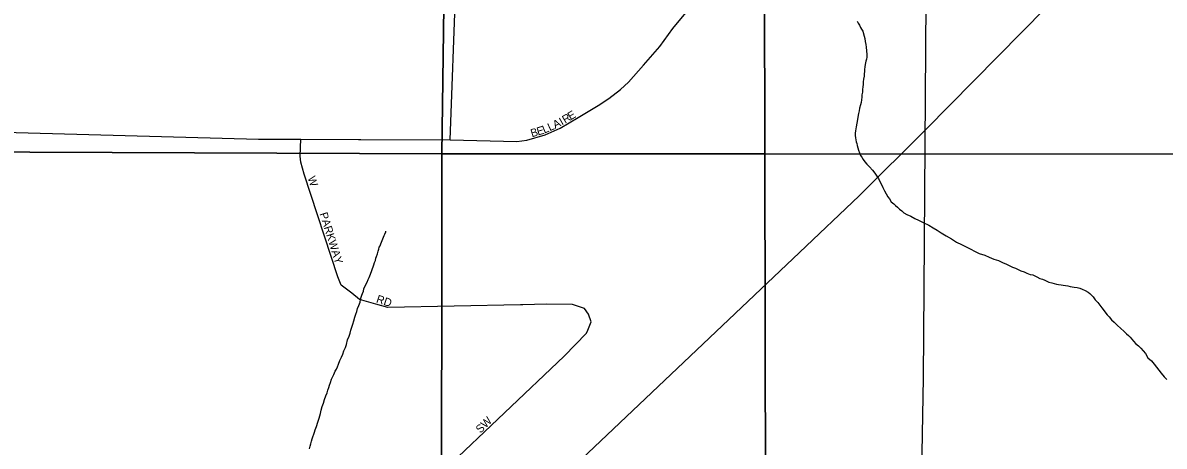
# Model space of a CAD drawing. Extents: x 2010165 to 2382125, y 1060529 to 1407316.
# Drawn here: x 2160411 to 2167540, y 1249702 to 1252344 of the extents above; entities that cross this region are included whole.
import ezdxf

# ---------------------------------------------------------------- set-up
doc = ezdxf.new("R2010")
doc.units = 0
for name, color, linetype in [('GM_X_City_Street', 7, 'Continuous'), ('GM_X_City_Street_Text', 7, 'Continuous'), ('GM_X_Minor_River', 7, 'Continuous'), ('GM_X_Rail_Line', 7, 'Continuous'), ('GM_X_Section', 7, 'Continuous')]:
    doc.layers.add(name, color=color, linetype=linetype)

msp = doc.modelspace()

# ---------------------------------------------------------------- linework, layer by layer
at = {"layer": 'GM_X_City_Street'}
for points in [[(2166040.5, 1250681.1), (2166057.9, 1253083), (2166069.7, 1255624.9), (2166069.8, 1255651), (2166070.7, 1255836.5), (2166071.2, 1255936.5)], [(2163080.1, 1251612.9), (2163115.9, 1252571.4), (2163119.5, 1253069)], [(2163496.1, 1251603.3), (2163560.1, 1251610.6), (2163674.3, 1251644.6), (2163768.2, 1251685.6), (2163880.8, 1251752), (2164005.3, 1251828.2), (2164070.7, 1251871.8), (2164143.3, 1251927.4), (2164194.1, 1251973.4), (2164288.5, 1252079.1), (2164391, 1252196.9), (2164471.6, 1252308.8), (2164562.1, 1252418.7), (2164632.1, 1252497.1), (2164766.3, 1252622.7), (2164969.8, 1252795), (2165154.8, 1252913.2), (2165318.9, 1252985.5), (2165474.8, 1253026.5), (2165602.8, 1253047.8), (2165855.7, 1253064.7), (2165985, 1253068.5), (2166057.9, 1253083)], [(2158103.5, 1251657.6), (2160216.5, 1251662.9), (2161884, 1251618.6), (2161907.3, 1251618.5)], [(2161907.3, 1251618.5), (2162148.1, 1251617.3), (2162508, 1251615.7), (2162522.4, 1251615.6)], [(2163519.3, 1250583.9), (2162691.5, 1250566.8), (2162615.5, 1250588.9), (2162513.5, 1250617.2), (2162465.6, 1250657.3), (2162399.7, 1250707.6), (2162377.8, 1250757.7), (2162167.5, 1251399.5), (2162147.7, 1251473.7), (2162143.8, 1251511.8), (2162148.1, 1251617.3)], [(2162522.4, 1251615.6), (2163080.1, 1251612.9), (2163496.1, 1251603.3)], [(2165985.8, 1247339.9), (2165992, 1247552), (2166036.5, 1250127.7), (2166040.5, 1250681.1)], [(2163939.3, 1250425.2), (2163960.2, 1250478.4), (2163944.3, 1250526.6), (2163920.4, 1250560.7), (2163844.4, 1250586.9), (2163680.3, 1250587.2), (2163535, 1250584.2), (2163519.3, 1250583.9)], [(2162300.8, 1248849), (2163793.4, 1250264.2), (2163931.9, 1250406.3), (2163939.3, 1250425.2)]]:
    msp.add_lwpolyline(points, dxfattribs=at)
at = {"layer": 'GM_X_Minor_River'}
for points in [[(2165621.6, 1252354.8), (2165627.9, 1252340.8), (2165636.1, 1252328.9), (2165642.4, 1252315), (2165650.6, 1252303.1), (2165656.9, 1252291.2), (2165665.5, 1252261.3), (2165669.8, 1252245.3), (2165672.1, 1252227.3), (2165676.5, 1252209.3), (2165678.8, 1252191.3), (2165681.2, 1252169.2), (2165683.7, 1252145.2), (2165682, 1252129.1), (2165680.2, 1252117.1), (2165676.4, 1252104.9), (2165674.6, 1252094.9), (2165672.8, 1252082.8), (2165671.1, 1252068.7), (2165669.3, 1252052.6), (2165667.6, 1252038.5), (2165665.8, 1252026.5), (2165666.1, 1252010.4), (2165662.4, 1251992.3), (2165660.7, 1251976.2), (2165659.1, 1251958.1), (2165657.3, 1251944), (2165655.6, 1251927.9), (2165655.9, 1251911.9), (2165652.2, 1251893.7), (2165652.5, 1251879.7)], [(2165652.5, 1251879.7), (2165648.8, 1251863.6), (2165647.1, 1251847.5), (2165643.4, 1251831.3), (2165637.7, 1251811.2), (2165634, 1251795), (2165630.3, 1251776.9), (2165619.4, 1251718.5), (2165615.8, 1251694.3), (2165612.3, 1251670.2), (2165610.5, 1251654.1), (2165610.8, 1251640.1), (2165613.1, 1251626.1), (2165615.5, 1251602), (2165619.8, 1251590.1), (2165622, 1251578.1), (2165626.3, 1251564.1), (2165630.6, 1251548.1), (2165636.9, 1251532.2), (2165643.2, 1251516.2), (2165651.5, 1251504.4), (2165659.8, 1251490.5), (2165670.1, 1251476.6), (2165682.4, 1251460.8), (2165698.7, 1251445.1), (2165719.2, 1251423.4), (2165733.6, 1251405.6), (2165746, 1251387.8), (2165756.3, 1251371.9), (2165764.6, 1251354), (2165775, 1251334.1), (2165783.4, 1251316.2), (2165793.9, 1251294.3), (2165804.2, 1251276.5), (2165814.6, 1251258.6), (2165824.9, 1251244.8), (2165835.2, 1251226.9), (2165851.5, 1251215.2), (2165861.8, 1251203.3), (2165874, 1251193.5), (2165886.3, 1251181.7), (2165900.5, 1251169.9), (2165914.8, 1251158.2), (2165933, 1251148.5), (2165957.3, 1251136.9), (2165981.7, 1251123.3), (2166006, 1251111.7), (2166034.3, 1251098.2), (2166070.8, 1251080.9), (2166097.1, 1251065.3), (2166121.5, 1251049.7), (2166147.9, 1251032.2), (2166178.3, 1251014.7), (2166210.8, 1250995.2), (2166243.3, 1250975.8), (2166273.7, 1250960.3), (2166304.1, 1250944.8), (2166385.1, 1250904.2), (2166419.4, 1250892.8), (2166447.7, 1250881.3), (2166476, 1250869.8), (2166504.3, 1250860.4), (2166530.6, 1250848.8), (2166554.9, 1250837.2), (2166575.2, 1250827.6), (2166593.4, 1250819.9), (2166611.6, 1250812.2), (2166627.8, 1250804.5), (2166644, 1250796.8), (2166666.2, 1250789.2), (2166682.4, 1250781.5), (2166702.6, 1250773.8), (2166720.7, 1250770.2), (2166732.9, 1250764.4), (2166745, 1250758.6), (2166763.3, 1250748.9), (2166779.4, 1250743.2), (2166795.6, 1250737.5), (2166807.7, 1250731.7), (2166819.9, 1250725.9), (2166838.1, 1250720.2), (2166852.2, 1250716.5), (2166868.3, 1250712.8), (2166880.4, 1250711), (2166896.5, 1250709.3), (2166908.5, 1250707.5), (2166924.7, 1250703.8), (2166938.7, 1250702.1), (2166952.9, 1250698.3), (2166977, 1250694.8), (2166997.1, 1250691.2), (2167013.3, 1250687.4), (2167027.4, 1250681.7), (2167045.6, 1250674), (2167065.9, 1250662.4), (2167076.1, 1250654.5), (2167086.3, 1250644.7), (2167096.5, 1250632.8), (2167108.9, 1250615), (2167125.3, 1250599.3), (2167137.6, 1250581.4)], [(2162201.6, 1249684.3), (2162205.2, 1249702.4), (2162211, 1249716.6), (2162214.7, 1249732.7), (2162218.5, 1249746.8), (2162233.7, 1249789.3), (2162237.5, 1249803.4), (2162245.1, 1249825.6), (2162254.6, 1249851.9), (2162262.2, 1249876.1), (2162269.7, 1249906.4), (2162275.3, 1249926.5), (2162280.9, 1249948.7), (2162288.5, 1249970.9), (2162296.2, 1249993.2), (2162303.8, 1250015.4), (2162311.4, 1250035.6), (2162317.1, 1250051.8), (2162322.9, 1250067.9), (2162326.6, 1250082.1), (2162332.3, 1250100.2), (2162339.9, 1250120.4), (2162353.5, 1250148.8), (2162363.1, 1250169.1), (2162370.9, 1250183.2), (2162376.6, 1250197.4), (2162382.4, 1250213.6), (2162392, 1250235.8), (2162401.6, 1250258.1), (2162409.3, 1250276.3), (2162416.9, 1250296.5), (2162426.6, 1250316.8), (2162432.2, 1250336.9), (2162439.7, 1250365.2), (2162449.4, 1250387.4), (2162455, 1250407.6), (2162460.7, 1250425.8), (2162466.4, 1250444), (2162472, 1250464.2), (2162479.7, 1250484.4), (2162485.3, 1250506.6), (2162490.9, 1250524.7), (2162496.6, 1250542.9), (2162502.3, 1250561.1), (2162510, 1250579.3), (2162517.6, 1250601.5), (2162521.3, 1250617.6), (2162525.1, 1250631.8), (2162528.9, 1250643.9), (2162532.7, 1250654), (2162538.4, 1250670.1), (2162542.2, 1250684.2), (2162551.8, 1250706.5), (2162561.5, 1250724.8), (2162569.2, 1250743), (2162575, 1250755.1), (2162582.6, 1250775.3), (2162590.2, 1250797.6), (2162596, 1250809.7), (2162599.8, 1250821.8), (2162603.6, 1250833.9), (2162607.3, 1250848.1), (2162613.1, 1250860.2), (2162616.9, 1250874.3), (2162620.7, 1250886.4), (2162626.4, 1250902.6), (2162630.1, 1250918.7), (2162635.9, 1250930.9), (2162637.7, 1250943), (2162643.5, 1250953.1), (2162647.3, 1250965.2), (2162651.1, 1250975.3), (2162655, 1250985.4), (2162668.4, 1251015.8), (2162672.3, 1251025.9), (2162678, 1251040.1), (2162678, 1251040.1), (2162677.9, 1251044.1)], [(2167137.6, 1250581.4), (2167150, 1250565.6), (2167184.9, 1250522.1), (2167197.2, 1250508.3), (2167211.6, 1250490.5), (2167227.9, 1250474.8), (2167248.4, 1250455.1), (2167266.8, 1250437.4), (2167291.2, 1250417.8), (2167305.5, 1250402), (2167317.8, 1250392.2), (2167328, 1250382.4), (2167338.2, 1250370.5), (2167348.5, 1250356.7), (2167362.9, 1250340.9), (2167379.2, 1250327.2), (2167393.5, 1250313.4), (2167409.8, 1250297.6), (2167424.2, 1250279.8), (2167438.7, 1250254), (2167461.2, 1250234.4), (2167477.6, 1250214.6), (2167492, 1250194.8), (2167506.4, 1250177.1), (2167520.8, 1250157.3), (2167539.3, 1250135.5), (2167557.7, 1250117.8)]]:
    msp.add_lwpolyline(points, dxfattribs=at)
at = {"layer": 'GM_X_Rail_Line'}
msp.add_lwpolyline([(2163899.7, 1249621.2), (2164579, 1250264.4), (2165263.2, 1250911.1), (2165635.3, 1251264.9), (2166051.9, 1251677.4), (2166800.4, 1252436.5), (2167547.9, 1253158.8)], dxfattribs=at)
at = {"layer": 'GM_X_Section'}
for points in [[(2157370.9, 1256894.4), (2163100.3, 1256876.5), (2163029.2, 1251527.1), (2157362.6, 1251549)], [(2163100.3, 1256876.5), (2165035.2, 1256877), (2165045.2, 1251526.2), (2163029.2, 1251527.1)], [(2165035.2, 1256877), (2168985.6, 1256877.9), (2168987.3, 1254287.1), (2168992.7, 1251699.5), (2168993.1, 1251524.5), (2165045.2, 1251526.2)], [(2157362.6, 1251549), (2163029.2, 1251527.1), (2163024.8, 1246131), (2162427.3, 1246126.4), (2159787.4, 1246122.3), (2157328.9, 1246108.9)], [(2163029.2, 1251527.1), (2165045.2, 1251526.2), (2165055.4, 1246148.6), (2163024.8, 1246131)], [(2165045.2, 1251526.2), (2168993.1, 1251524.5), (2168999.8, 1249196.9), (2169019.3, 1246178.7), (2165055.4, 1246148.6)]]:
    msp.add_lwpolyline(points, close=True, dxfattribs=at)

# ---------------------------------------------------------------- texts
at = {"layer": 'GM_X_City_Street_Text'}
for s, rotation, p in [('A', 26.48431, (2163736.2, 1251681.9)), ('I', 29.80771, (2163778.4, 1251703)), ('R', 30.46895, (2163798, 1251714.2)), ('E', 30.67469, (2163832.3, 1251734.4)), ('B', 16.34568, (2163590.9, 1251629.3)), ('E', 16.34129, (2163628.9, 1251640.4)), ('L', 22.30973, (2163668, 1251652.2)), ('L', 24.63734, (2163702.6, 1251666.4)), ('W', 288.44042, (2162189.6, 1251377.3)), ('PARKWAY', 287.40231, (2162264.4, 1251152.8)), ('RD', 341.56505, (2162614.8, 1250600)), ('SW', 45.00728, (2163269.6, 1249779.4))]:
    msp.add_text(s, height=50, rotation=rotation, dxfattribs=at).set_placement(p)

doc.saveas('drawing.dxf')
